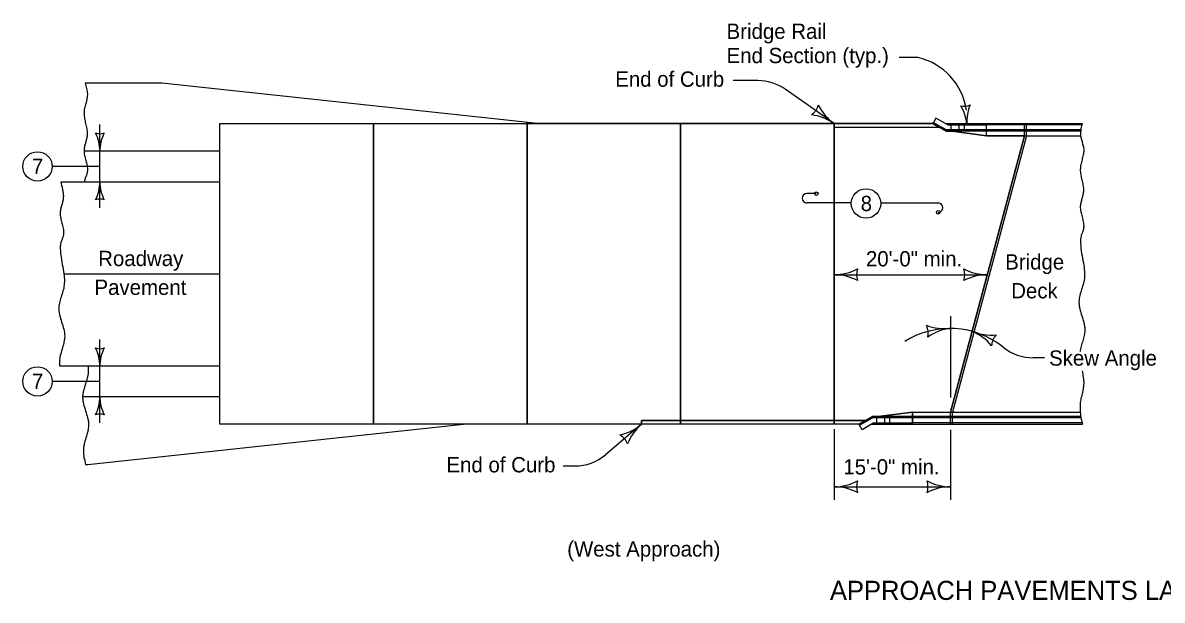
# Model space of a CAD drawing. Extents: x 10130 to 81668, y 5440 to 21644.
# Drawn here: x 17945 to 19139, y 12089 to 12694 of the extents above; entities that cross this region are included whole.
import ezdxf

# ---------------------------------------------------------------- set-up
doc = ezdxf.new("R2010")
doc.units = 0
for name, color, linetype in [('dsnstdblockInterim', 7, 'Continuous'), ('dsnStdBlockModified', 7, 'Continuous'), ('dsnStdBlockNotModified', 7, 'Continuous'), ('dsnStdBorder', 7, 'Continuous'), ('dsnstdModifiedBlock', 7, 'Continuous')]:
    doc.layers.add(name, color=color, linetype=linetype)

msp = doc.modelspace()

# ---------------------------------------------------------------- linework, layer by layer
at = {"layer": 'dsnstdblockInterim'}
for p, q in [((18898.5, 12588.6), (18899.2, 12589.8)), ((18898.5, 12588.6), (18912.4, 12580.6)), ((18901.8, 12594.4), (18899.2, 12589.8)), ((18899.2, 12589.8), (18912.8, 12581.9)), ((18914.2, 12587.3), (18901.8, 12594.4)), ((18911.9, 12588.6), (18954.8, 12588.6)), ((18917.3, 12587.3), (18917.3, 12580.6)), ((18925.8, 12587.3), (18925.8, 12580.6)), ((18931.2, 12587.3), (18931.2, 12580.6)), ((18954.8, 12588.6), (19054.9, 12588.6)), ((18954.8, 12575.9), (18954.8, 12588.6)), ((19054.5, 12587.3), (18954.8, 12587.3)), ((18994.6, 12575.9), (18994.6, 12588.6)), ((18994.6, 12575.9), (18994.6, 12588.6)), ((18996.6, 12575.9), (18996.6, 12588.6)), ((18954.8, 12580.6), (18912.4, 12580.6)), ((18954.8, 12581.9), (18912.8, 12581.9)), ((18994.6, 12575.9), (18917, 12286.4)), ((18994.6, 12575.9), (18917, 12286.4)), ((18954.8, 12575.9), (18918.8, 12580.6)), ((19053.5, 12581.9), (18954.8, 12581.9)), ((19053.4, 12580.6), (18954.8, 12580.6)), ((18954.8, 12575.9), (19053.3, 12575.9)), ((18877.2, 12286.4), (18841.2, 12281.7)), ((18877.2, 12286.4), (18877.2, 12273.6)), ((18877.2, 12275), (18877.2, 12286.4)), ((18877.2, 12286.4), (19053, 12286.4)), ((18917, 12273.6), (18917, 12286.4)), ((18917, 12273.6), (18917, 12286.4)), ((18919, 12273.6), (18919, 12286.4)), ((18820.9, 12273.6), (18834.8, 12281.7)), ((18820.9, 12273.6), (18821.6, 12272.5)), ((18821.6, 12272.5), (18835.2, 12280.3)), ((18824.3, 12267.8), (18821.6, 12272.5)), ((18836.6, 12275), (18824.3, 12267.8)), ((18834.3, 12273.6), (18877.2, 12273.6)), ((18877.2, 12281.7), (18834.8, 12281.7)), ((18877.2, 12280.3), (18835.2, 12280.3)), ((18839.7, 12275), (18839.7, 12281.7)), ((18848.2, 12275), (18848.2, 12281.7)), ((18853.6, 12275), (18853.6, 12281.7)), ((19053.5, 12281.7), (18877.2, 12281.7)), ((19053.7, 12280.3), (18877.2, 12280.3)), ((19054.8, 12275), (18877.2, 12275)), ((18877.2, 12273.6), (19055.3, 12273.6))]:
    msp.add_line(p, q, dxfattribs=at)
for points in [[(18914.2, 12587.3), (18954.8, 12587.3), (18954.8, 12587.3), (18954.8, 12587.3)], [(18836.6, 12275), (18877.2, 12275), (18877.2, 12275), (18877.2, 12275)]]:
    msp.add_lwpolyline(points, dxfattribs=at)
at = {"layer": 'dsnStdBlockNotModified'}
for centre in [(18776.4, 12515.2), (18904.1, 12495.6)]:
    msp.add_circle(centre, 1.78, dxfattribs=at)
for centre, radius, start, end in [((18931.5, 12623.3), 16.4, 256.6331, 292.0998), ((18891.8, 12584.5), 42.5, 4.3665, 32.439), ((18976.6, 12591), 42.5, 156.294, 184.3665)]:
    msp.add_arc(centre, radius, start, end, dxfattribs=at)
at = {"layer": 'dsnStdBorder'}
for p, q in [((18882.9, 12657.9), (18863.3, 12657.9)), ((18090.7, 12630.9), (18010.3, 12630.9)), ((18484.3, 12588.6), (18090.7, 12630.9)), ((18715.1, 12633.6), (18689.3, 12633.6)), ((18795, 12588.6), (18743.8, 12624.5)), ((18025.8, 12500.3), (18025.8, 12587.7)), ((19054.8, 12588.6), (19054.9, 12588.6)), ((18151.6, 12559.8), (18009.2, 12559.8)), ((17996.3, 12543.7), (17975.7, 12543.7)), ((18025.8, 12543.7), (17996.3, 12543.7)), ((17984.8, 12527.6), (18151.6, 12527.6)), ((18776.4, 12515.2), (18766.6, 12515.2)), ((18813.1, 12505.4), (18766.6, 12505.4)), ((18843.8, 12505.4), (18904.1, 12505.4)), ((17988, 12431.1), (18151.6, 12431.1)), ((18795, 12430.3), (18955.6, 12430.3)), ((18917, 12386.9), (18917, 12301.5)), ((18025.8, 12275.1), (18025.8, 12362.5)), ((18151.6, 12334.6), (17983.7, 12334.6)), ((19015.5, 12343.2), (19003.7, 12343.2)), ((17996.3, 12318.5), (17975.7, 12318.5)), ((18025.8, 12318.5), (17996.3, 12318.5)), ((18151.6, 12302.5), (18007.7, 12302.5)), ((18013.1, 12231.4), (18406.7, 12273.6)), ((18593.4, 12273.6), (18555.7, 12241.7)), ((19054.9, 12274.7), (19055.3, 12273.6)), ((18795, 12268.4), (18795, 12194.5)), ((18917, 12267.7), (18917, 12194.5)), ((18511.1, 12229.9), (18523.4, 12229.9)), ((18795, 12208.1), (18917, 12208.1))]:
    msp.add_line(p, q, dxfattribs=at)
for points in [[(18151.6, 12273.6), (18151.6, 12588.6), (18312.4, 12588.6), (18312.4, 12273.6)], [(18406.7, 12273.6), (18406.7, 12273.6), (18312.4, 12273.6), (18312.4, 12588.6), (18473.3, 12588.6), (18473.3, 12273.6)], [(18473.3, 12273.6), (18473.3, 12588.6), (18484.3, 12588.6), (18484.3, 12588.6), (18634.1, 12588.6), (18634.1, 12277.7), (18593.4, 12277.7), (18593.4, 12273.6)], [(18795, 12277.7), (18634.1, 12277.7), (18634.1, 12588.6), (18795, 12588.6), (18795, 12584.6), (18795, 12584.6)], [(18795, 12588.6), (18795, 12584.6), (18795, 12584.6), (18795, 12588.6)], [(18898.5, 12588.6), (18905.5, 12584.6), (18795, 12584.6), (18795, 12588.6)], [(18912.4, 12580.6), (18905.5, 12584.6), (18795, 12584.6), (18795, 12277.7), (18827.9, 12277.7), (18834.8, 12281.7), (18841.2, 12281.7), (18877.2, 12286.4), (18917, 12286.4), (18994.6, 12575.9), (18954.8, 12575.9), (18918.8, 12580.6)], [(18593.4, 12273.6), (18593.4, 12277.7), (18634.1, 12277.7), (18634.1, 12273.6)], [(18634.1, 12273.6), (18634.1, 12277.7), (18795, 12277.7), (18795, 12273.6)], [(18827.9, 12277.7), (18820.9, 12273.6), (18795, 12273.6), (18795, 12277.7)]]:
    msp.add_lwpolyline(points, close=True, dxfattribs=at)
for centre in [(17960.4, 12543.7), (18828.5, 12504.9), (18828.5, 12504.9), (17960.4, 12318.5)]:
    msp.add_circle(centre, 15.4, dxfattribs=at)
for centre, radius, start, end in [((18867.7, 12592.9), 66.7, 8.4828, 76.8823), ((18715.1, 12583.6), 50, 54.9382, 90), ((18759.1, 12613.8), 20.2, 307.2049, 342.6716), ((18825, 12631.4), 52.2, 206.8657, 234.9382), ((18765, 12545.9), 52.2, 54.9382, 83.0107), ((18025.8, 12593.5), 15.5, 252.2666, 287.7334), ((17985.6, 12559.8), 40.2, 0, 28.0725), ((18065.9, 12559.8), 40.2, 151.9275, 180), ((17985.6, 12527.6), 40.2, 331.9275, 0), ((18065.9, 12527.6), 40.2, 180, 208.0725), ((18766.6, 12510.3), 4.92, 90, 270), ((18025.8, 12494), 15.5, 72.2666, 107.7334), ((18904.1, 12500.5), 4.92, 270, 90), ((18795, 12482.5), 52.2, 270, 298.0725), ((18795, 12378.1), 52.2, 61.9275, 90), ((18838.8, 12430.3), 20.2, 162.2666, 197.7334), ((18911.8, 12430.3), 20.2, 342.2666, 17.7334), ((18955.6, 12482.5), 52.2, 241.9275, 270), ((18955.6, 12378.1), 52.2, 90, 118.0725), ((18916.5, 12285.3), 88.7, 51.0377, 122.325), ((18873.5, 12368.8), 20.2, 349.0765, 24.5432), ((18910.8, 12425.9), 52.2, 248.7374, 276.8099), ((18923.2, 12322.2), 52.2, 96.8099, 124.8824), ((18959.7, 12419.2), 52.2, 247.4953, 275.5678), ((18919.7, 12322.7), 52.2, 39.4229, 67.4953), ((18980.1, 12354.2), 20.2, 139.762, 175.2287), ((18025.8, 12368.3), 15.5, 252.2666, 287.7334), ((17985.6, 12334.6), 40.2, 0, 28.0725), ((18065.9, 12334.6), 40.2, 151.9275, 180), ((19003.7, 12393.2), 50, 231.0377, 270), ((17985.6, 12302.5), 40.2, 331.9275, 0), ((18065.9, 12302.5), 40.2, 180, 208.0725), ((18025.8, 12268.8), 15.5, 72.2666, 107.7334), ((18559.7, 12313.5), 52.2, 282.1746, 310.2471), ((18627.1, 12233.8), 52.2, 130.2471, 158.3196), ((18560, 12245.3), 20.2, 22.5137, 57.9804), ((18523.4, 12279.9), 50, 270, 310.2471), ((18795, 12260.3), 52.2, 270, 298.0725), ((18838.8, 12208.1), 20.2, 162.2666, 197.7334), ((18873.2, 12208.1), 20.2, 342.2667, 17.7334), ((18917, 12260.3), 52.2, 241.9275, 270), ((18795, 12155.9), 52.2, 61.9275, 90), ((18917, 12155.9), 52.2, 90, 118.0725)]:
    msp.add_arc(centre, radius, start, end, dxfattribs=at)
for points in [[(19054.8, 12588.6), (19053.7, 12583.6), (19053.4, 12581.1), (19053.2, 12578.6), (19053.6, 12574.1), (19054.8, 12569.7), (19056, 12565.3), (19056.6, 12560.8), (19056, 12555.7), (19054.8, 12550.6), (19053.6, 12545.5), (19053, 12540.4), (19053.5, 12535), (19054.7, 12529.5), (19055.8, 12524.1), (19056.3, 12518.6), (19055.8, 12514.4), (19054.7, 12510.1), (19053.6, 12505.8), (19053, 12501.6), (19053.5, 12496.3), (19054.8, 12490.9), (19056.1, 12485.6), (19056.6, 12480.3), (19056, 12477), (19054.9, 12473.9), (19053.8, 12470.7), (19053.2, 12467.5), (19053.3, 12462.6), (19053.7, 12457.6), (19055.3, 12447.7), (19056.9, 12437.7), (19057.4, 12430.3), (19057.4, 12427.9), (19056.3, 12421.5), (19054.4, 12415.1), (19052.5, 12408.6), (19051.6, 12402.2), (19051.8, 12398.5), (19052.4, 12394.7), (19054.6, 12387.2), (19056.8, 12379.7), (19057.5, 12376), (19057.7, 12374.1), (19057.7, 12372.2), (19057.1, 12366.6), (19055.6, 12361.1), (19054, 12355.5), (19052.7, 12350)], [(19054.8, 12329.7), (19056.1, 12323.1), (19056.6, 12316.5), (19055.9, 12310.3), (19054.5, 12304), (19053.1, 12297.8), (19052.7, 12291.6), (19052.9, 12287.3), (19053.3, 12283.1), (19054.9, 12274.7)]]:
    msp.add_spline(points, degree=3, dxfattribs=at)
at = {"layer": 'dsnstdModifiedBlock'}
for p, q in [((18151.6, 12273.6), (18151.6, 12588.6)), ((18151.6, 12588.6), (18312.4, 12588.6)), ((18151.6, 12559.8), (18151.6, 12588.6)), ((18151.6, 12588.6), (18484.3, 12588.6)), ((18312.4, 12273.6), (18312.4, 12588.6)), ((18312.4, 12588.6), (18473.3, 12588.6)), ((18473.3, 12273.6), (18473.3, 12589.8)), ((18898.5, 12588.6), (18473.3, 12588.6)), ((18634.1, 12273.6), (18634.1, 12588.6)), ((18795, 12588.6), (18795, 12584.6)), ((18795, 12273.6), (18795, 12588.6)), ((18905.5, 12584.6), (18795, 12584.6)), ((18898.5, 12588.6), (18912.4, 12580.6)), ((18912.4, 12580.6), (18918.8, 12580.6)), ((18918.8, 12580.6), (18954.8, 12575.9)), ((18996.6, 12575.9), (18919, 12286.4)), ((18954.8, 12575.9), (18994.6, 12575.9)), ((18994.6, 12575.9), (18955.8, 12431.1)), ((18151.6, 12527.6), (18151.6, 12559.8)), ((18917, 12286.4), (18955.8, 12431.1)), ((18151.6, 12273.6), (18151.6, 12302.5)), ((18841.2, 12281.7), (18877.2, 12286.4)), ((18877.2, 12286.4), (18917, 12286.4)), ((18406.7, 12273.6), (18151.6, 12273.6)), ((18820.9, 12273.6), (18151.6, 12273.6)), ((18827.9, 12277.7), (18593.4, 12277.7)), ((18593.4, 12273.6), (18593.4, 12277.7)), ((18820.9, 12273.6), (18834.8, 12281.7)), ((18834.8, 12281.7), (18841.2, 12281.7)), ((18010.7, 12231.4), (18013.1, 12231.4))]:
    msp.add_line(p, q, dxfattribs=at)
for points in [[(18010.3, 12630.9), (18011.9, 12625.4), (18012.7, 12619.9), (18012.6, 12617.3), (18012.2, 12614.8), (18011, 12609.7), (18009.7, 12604.6), (18009.2, 12599.5), (18009.7, 12594), (18010.8, 12588.6), (18012, 12583.1), (18012.5, 12577.7), (18012, 12573.4), (18010.9, 12569.1), (18009.8, 12564.9), (18009.2, 12560.6), (18009.7, 12555.3), (18011, 12550), (18012.3, 12544.6), (18012.7, 12539.3), (18012.2, 12536.1), (18011.1, 12532.9), (18010, 12529.7), (18009.5, 12527.6)], [(17984.8, 12527.6), (17986.5, 12519.9), (17987.2, 12516), (17987.5, 12512.1), (17987, 12507.8), (17985.9, 12503.6), (17984.7, 12499.3), (17984.2, 12495.1), (17984.7, 12489.7), (17986, 12484.4), (17987.3, 12479.1), (17987.7, 12473.7), (17987.2, 12470.5), (17986.1, 12467.3), (17985, 12464.1), (17984.4, 12460.9), (17984.4, 12456), (17984.8, 12451.1), (17986.4, 12441.1), (17988, 12431.2), (17988.6, 12423.8), (17988.5, 12421.4), (17987.5, 12414.9), (17985.6, 12408.5), (17983.7, 12402.1), (17982.7, 12395.7), (17982.9, 12391.9), (17983.6, 12388.2), (17985.7, 12380.7), (17987.9, 12373.2), (17988.9, 12365.7), (17988.6, 12362.3), (17988, 12359), (17986.1, 12352.3), (17984.3, 12345.6), (17983.4, 12338.9), (17983.7, 12334.6)], [(18013.4, 12334.6), (18013.5, 12328.4), (18013.2, 12325.2), (18012.5, 12322), (18010.6, 12315.6), (18008.7, 12309.2), (18008, 12306), (18007.8, 12304.3), (18007.7, 12302.7), (18007.9, 12299), (18008.6, 12295.2), (18010.8, 12287.7), (18012.9, 12280.2), (18013.7, 12276.5), (18013.8, 12274.6), (18013.9, 12272.7), (18013.6, 12269.4), (18013, 12266), (18011.1, 12259.3), (18009.3, 12252.7), (18008.7, 12249.3), (18008.5, 12247.6), (18008.5, 12246), (18009.1, 12238.8), (18010.7, 12231.5), (18010.7, 12231.4)]]:
    msp.add_spline(points, degree=3, dxfattribs=at)

# ---------------------------------------------------------------- texts
at = {"layer": 'dsnStdBlockModified'}
for s, p in [('End of Curb', (18565.7, 12627.2)), ('7', (17954.5, 12535.7)), ('8', (18822.9, 12496.9)), ('Roadway', (18024, 12439.3)), ('20\'-0" min.', (18828.4, 12439)), ('Bridge', (18974.3, 12435.7)), ('Pavement', (18020.1, 12409.1)), ('Deck', (18980.6, 12405.5)), ('Skew Angle', (19020.3, 12335)), ('7', (17954.5, 12310.5)), ('End of Curb', (18388.9, 12223.2)), ('15\'-0" min.', (18804.7, 12221)), ('(West Approach)', (18515.4, 12135))]:
    msp.add_text(s, height=16, dxfattribs=at).set_placement(p)
at = {"layer": 'dsnStdBlockNotModified'}
msp.add_text('APPROACH PAVEMENTS LAYOUT AT A SKEW', height=20, dxfattribs=at).set_placement((18790.7, 12089.6))
at = {"layer": 'dsnStdBorder'}
for s, p in [('Bridge Rail', (18682.4, 12677.3)), ('End Section (typ.)', (18682.4, 12651.9))]:
    msp.add_text(s, height=16, dxfattribs=at).set_placement(p)

doc.saveas('drawing.dxf')
